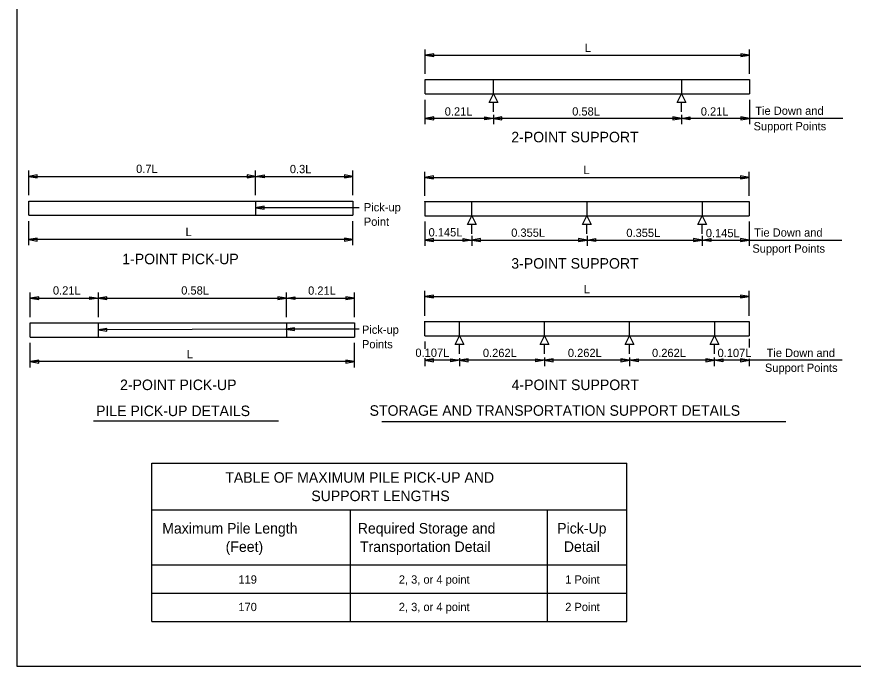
# Model space of a CAD drawing. Extents: x 120517.2 to 120592, y 120519.3 to 120603.1.
# Drawn here: x 120521.21 to 120541.57, y 120571.22 to 120587.02 of the extents above; entities that cross this region are included whole.
import ezdxf

# ---------------------------------------------------------------- set-up
doc = ezdxf.new("R2010")
doc.units = 0
for name, color, linetype in [('ActivePts-ConstElements', 7, 'Continuous'), ('AdhocPoint_dp', 7, 'Continuous'), ('PlotBorder_dp', 7, 'Continuous'), ('TextMisc', 7, 'Continuous')]:
    doc.layers.add(name, color=color, linetype=linetype)

msp = doc.modelspace()

# ---------------------------------------------------------------- linework, layer by layer
at = {"layer": 'ActivePts-ConstElements'}
msp.add_lwpolyline([(120521.209, 120571.217), (120562.259, 120571.217), (120562.259, 120597.163), (120521.209, 120597.163)], close=True, dxfattribs=at)
at = {"layer": 'PlotBorder_dp'}
for p, q in [((120531.151, 120585.633), (120531.151, 120586.226)), ((120539.041, 120585.633), (120539.041, 120586.226)), ((120531.151, 120586.086), (120539.041, 120586.086)), ((120531.151, 120584.408), (120531.151, 120585.004)), ((120539.041, 120585.004), (120539.041, 120584.408)), ((120532.81, 120584.704), (120532.81, 120584.936)), ((120537.386, 120584.704), (120537.386, 120584.936)), ((120532.808, 120584.638), (120532.808, 120584.408)), ((120537.385, 120584.636), (120537.385, 120584.408)), ((120541.313, 120584.548), (120531.151, 120584.548)), ((120521.501, 120582.678), (120521.501, 120583.277)), ((120527.023, 120582.678), (120527.023, 120583.277)), ((120529.39, 120582.678), (120529.39, 120583.277)), ((120531.141, 120582.664), (120531.141, 120583.252)), ((120539.03, 120582.664), (120539.03, 120583.252)), ((120521.501, 120583.137), (120529.39, 120583.137)), ((120531.141, 120583.112), (120539.03, 120583.112)), ((120531.141, 120582.524), (120531.141, 120582.532)), ((120532.283, 120582.524), (120532.283, 120582.527)), ((120535.085, 120582.524), (120535.085, 120582.531)), ((120529.54, 120582.376), (120527.023, 120582.376)), ((120521.501, 120581.46), (120521.501, 120582.048)), ((120529.39, 120581.46), (120529.39, 120582.05)), ((120531.141, 120582.036), (120531.141, 120581.447)), ((120532.286, 120581.736), (120532.286, 120581.967)), ((120535.086, 120581.736), (120535.086, 120581.967)), ((120537.888, 120581.736), (120537.888, 120581.967)), ((120539.03, 120582.036), (120539.03, 120581.447)), ((120529.39, 120581.6), (120521.501, 120581.6)), ((120531.141, 120581.587), (120541.285, 120581.587)), ((120532.285, 120581.691), (120532.285, 120581.447)), ((120535.088, 120581.691), (120535.088, 120581.447)), ((120537.89, 120581.691), (120537.89, 120581.447)), ((120521.538, 120579.713), (120521.538, 120580.313)), ((120523.195, 120579.713), (120523.195, 120580.313)), ((120527.771, 120579.713), (120527.771, 120580.313)), ((120529.428, 120579.713), (120529.428, 120580.313)), ((120531.141, 120579.747), (120531.141, 120580.354)), ((120539.03, 120579.747), (120539.03, 120580.354)), ((120521.538, 120580.173), (120529.428, 120580.173)), ((120531.141, 120580.214), (120539.03, 120580.214)), ((120531.141, 120579.607), (120531.141, 120579.615)), ((120532.283, 120579.607), (120532.283, 120579.61)), ((120535.085, 120579.607), (120535.085, 120579.613)), ((120527.761, 120579.42), (120523.195, 120579.403)), ((120529.546, 120579.42), (120527.761, 120579.42)), ((120521.538, 120578.489), (120521.538, 120579.085)), ((120529.428, 120578.489), (120529.428, 120579.085)), ((120531.141, 120579.118), (120531.141, 120578.938)), ((120539.03, 120579.181), (120539.03, 120578.971)), ((120531.986, 120578.818), (120531.986, 120579.05)), ((120534.053, 120578.818), (120534.053, 120579.05)), ((120536.12, 120578.818), (120536.12, 120579.05)), ((120538.188, 120578.818), (120538.188, 120579.05)), ((120531.141, 120578.714), (120531.141, 120578.522)), ((120541.298, 120578.662), (120531.141, 120578.662)), ((120531.985, 120578.717), (120531.985, 120578.522)), ((120534.051, 120578.73), (120534.051, 120578.522)), ((120536.118, 120578.73), (120536.118, 120578.522)), ((120538.185, 120578.728), (120538.185, 120578.522)), ((120539.03, 120578.7), (120539.03, 120578.522)), ((120529.428, 120578.629), (120521.538, 120578.629)), ((120531.985, 120578.587), (120531.985, 120578.522)), ((120536.121, 120578.522), (120536.121, 120578.522)), ((120527.583, 120577.177), (120523.078, 120577.177)), ((120530.09, 120577.17), (120539.927, 120577.17)), ((120524.495, 120576.156), (120536.056, 120576.156)), ((120524.495, 120572.305), (120524.495, 120576.156)), ((120536.056, 120572.305), (120536.056, 120576.156)), ((120524.495, 120575.02), (120536.056, 120575.02)), ((120529.328, 120572.305), (120529.328, 120575.02)), ((120534.123, 120572.305), (120534.123, 120575.02)), ((120524.495, 120573.684), (120536.056, 120573.684)), ((120524.495, 120572.995), (120536.056, 120572.995)), ((120524.495, 120572.305), (120536.056, 120572.305))]:
    msp.add_line(p, q, dxfattribs=at)
for points in [[(120531.151, 120586.086), (120531.36, 120586.051), (120531.36, 120586.122)], [(120539.041, 120586.086), (120538.833, 120586.122), (120538.833, 120586.051)], [(120532.808, 120585.144), (120532.913, 120584.936), (120532.703, 120584.936)], [(120537.385, 120585.144), (120537.49, 120584.936), (120537.28, 120584.936)], [(120531.151, 120584.548), (120531.36, 120584.513), (120531.36, 120584.584)], [(120532.808, 120584.548), (120532.6, 120584.513), (120532.6, 120584.584)], [(120532.808, 120584.548), (120533.016, 120584.513), (120533.016, 120584.584)], [(120537.385, 120584.548), (120537.176, 120584.584), (120537.176, 120584.513)], [(120537.385, 120584.548), (120537.593, 120584.584), (120537.593, 120584.513)], [(120539.041, 120584.548), (120538.833, 120584.584), (120538.833, 120584.513)], [(120521.501, 120583.137), (120521.71, 120583.102), (120521.71, 120583.173)], [(120527.023, 120583.137), (120526.815, 120583.173), (120526.815, 120583.102)], [(120527.023, 120583.137), (120527.231, 120583.173), (120527.231, 120583.102)], [(120529.39, 120583.137), (120529.182, 120583.173), (120529.182, 120583.102)], [(120531.141, 120583.112), (120531.35, 120583.077), (120531.35, 120583.148)], [(120539.03, 120583.112), (120538.821, 120583.148), (120538.821, 120583.077)], [(120527.023, 120582.376), (120527.231, 120582.341), (120527.231, 120582.411)], [(120532.285, 120582.176), (120532.39, 120581.967), (120532.18, 120581.967)], [(120535.085, 120582.176), (120535.19, 120581.967), (120534.98, 120581.967)], [(120537.886, 120582.176), (120537.991, 120581.967), (120537.781, 120581.967)], [(120521.501, 120581.6), (120521.71, 120581.564), (120521.71, 120581.635)], [(120529.39, 120581.6), (120529.182, 120581.635), (120529.182, 120581.564)], [(120531.141, 120581.587), (120531.35, 120581.552), (120531.35, 120581.623)], [(120532.285, 120581.587), (120532.076, 120581.552), (120532.076, 120581.623)], [(120532.285, 120581.587), (120532.493, 120581.552), (120532.493, 120581.623)], [(120535.088, 120581.587), (120534.88, 120581.623), (120534.88, 120581.552)], [(120535.088, 120581.587), (120535.296, 120581.623), (120535.296, 120581.552)], [(120537.89, 120581.587), (120537.681, 120581.623), (120537.681, 120581.552)], [(120537.89, 120581.587), (120538.098, 120581.623), (120538.098, 120581.552)], [(120539.03, 120581.587), (120538.821, 120581.623), (120538.821, 120581.552)], [(120521.538, 120580.173), (120521.746, 120580.138), (120521.746, 120580.208)], [(120523.195, 120580.173), (120522.987, 120580.138), (120522.987, 120580.208)], [(120523.195, 120580.173), (120523.403, 120580.138), (120523.403, 120580.208)], [(120527.771, 120580.173), (120527.563, 120580.208), (120527.563, 120580.138)], [(120527.771, 120580.173), (120527.98, 120580.208), (120527.98, 120580.138)], [(120529.428, 120580.173), (120529.22, 120580.208), (120529.22, 120580.138)], [(120531.141, 120580.214), (120531.35, 120580.178), (120531.35, 120580.249)], [(120539.03, 120580.214), (120538.821, 120580.249), (120538.821, 120580.178)], [(120523.195, 120579.403), (120523.403, 120579.369), (120523.403, 120579.439)], [(120527.761, 120579.42), (120527.97, 120579.385), (120527.97, 120579.455)], [(120531.985, 120579.258), (120532.09, 120579.05), (120531.88, 120579.05)], [(120534.051, 120579.258), (120534.156, 120579.05), (120533.946, 120579.05)], [(120536.118, 120579.258), (120536.223, 120579.05), (120536.013, 120579.05)], [(120538.186, 120579.258), (120538.291, 120579.05), (120538.081, 120579.05)], [(120521.538, 120578.629), (120521.746, 120578.594), (120521.746, 120578.665)], [(120529.428, 120578.629), (120529.22, 120578.665), (120529.22, 120578.594)], [(120531.141, 120578.662), (120531.35, 120578.626), (120531.35, 120578.697)], [(120531.985, 120578.662), (120531.776, 120578.626), (120531.776, 120578.697)], [(120531.985, 120578.662), (120532.193, 120578.626), (120532.193, 120578.697)], [(120534.051, 120578.662), (120533.843, 120578.626), (120533.843, 120578.697)], [(120534.051, 120578.662), (120534.26, 120578.626), (120534.26, 120578.697)], [(120536.118, 120578.662), (120535.91, 120578.697), (120535.91, 120578.626)], [(120536.125, 120578.662), (120536.333, 120578.697), (120536.333, 120578.626)], [(120538.185, 120578.662), (120537.976, 120578.697), (120537.976, 120578.626)], [(120538.185, 120578.662), (120538.393, 120578.697), (120538.393, 120578.626)], [(120539.03, 120578.662), (120538.821, 120578.697), (120538.821, 120578.626)]]:
    msp.add_lwpolyline(points, close=True, dxfattribs=at)
at = {"layer": 'TextMisc'}
for p, q in [((120531.151, 120585.493), (120539.041, 120585.493)), ((120531.151, 120585.144), (120531.151, 120585.493)), ((120532.808, 120585.144), (120532.808, 120585.493)), ((120537.385, 120585.493), (120537.385, 120585.144)), ((120539.041, 120585.493), (120539.041, 120585.144)), ((120531.151, 120585.144), (120539.041, 120585.144)), ((120521.501, 120582.538), (120529.39, 120582.538)), ((120521.501, 120582.19), (120521.501, 120582.538)), ((120527.023, 120582.538), (120527.023, 120582.19)), ((120529.39, 120582.538), (120529.39, 120582.19)), ((120531.141, 120582.524), (120539.03, 120582.524)), ((120531.141, 120582.524), (120531.141, 120582.176)), ((120532.283, 120582.176), (120532.283, 120582.524)), ((120532.285, 120582.176), (120532.285, 120582.524)), ((120535.085, 120582.524), (120535.085, 120582.176)), ((120535.233, 120582.524), (120539.03, 120582.524)), ((120537.886, 120582.524), (120537.886, 120582.176)), ((120539.03, 120582.524), (120539.03, 120582.176)), ((120521.501, 120582.19), (120529.39, 120582.19)), ((120531.141, 120582.176), (120539.03, 120582.176)), ((120521.538, 120579.573), (120529.428, 120579.573)), ((120521.538, 120579.225), (120521.538, 120579.573)), ((120523.195, 120579.225), (120523.195, 120579.573)), ((120527.771, 120579.573), (120527.771, 120579.225)), ((120529.428, 120579.573), (120529.428, 120579.225)), ((120531.141, 120579.607), (120539.03, 120579.607)), ((120531.141, 120579.258), (120531.141, 120579.607)), ((120531.985, 120579.258), (120531.985, 120579.607)), ((120534.051, 120579.258), (120534.051, 120579.607)), ((120535.233, 120579.607), (120539.03, 120579.607)), ((120536.118, 120579.258), (120536.118, 120579.607)), ((120538.186, 120579.607), (120538.186, 120579.258)), ((120539.03, 120579.607), (120539.03, 120579.258)), ((120521.538, 120579.225), (120529.428, 120579.225)), ((120531.141, 120579.258), (120539.03, 120579.258))]:
    msp.add_line(p, q, dxfattribs=at)

# ---------------------------------------------------------------- texts
at = {"layer": 'AdhocPoint_dp'}
for s, height, p in [('L', 0.202, (120535.031, 120586.163)), ('0.21L', 0.2016, (120531.624, 120584.616)), ('0.58L', 0.2016, (120534.726, 120584.617)), ('0.21L', 0.2016, (120537.856, 120584.617)), ('Tie Down and', 0.2016, (120539.182, 120584.634)), ('Support Points', 0.2016, (120539.14, 120584.258)), ('2-POINT SUPPORT', 0.256, (120533.244, 120583.966)), ('0.7L', 0.2016, (120524.114, 120583.221)), ('0.3L', 0.2016, (120527.855, 120583.215)), ('L', 0.202, (120535.001, 120583.192)), ('L', 0.202, (120525.318, 120581.684)), ('0.145L', 0.2016, (120531.231, 120581.676)), ('0.355L', 0.2016, (120533.242, 120581.667)), ('0.355L', 0.2016, (120536.044, 120581.662)), ('0.145L', 0.2016, (120537.978, 120581.658)), ('Tie Down and', 0.2016, (120539.156, 120581.67)), ('Support Points', 0.2016, (120539.111, 120581.28)), ('1-POINT PICK-UP', 0.256, (120523.777, 120581)), ('3-POINT SUPPORT', 0.256, (120533.244, 120580.892)), ('L', 0.202, (120535.01, 120580.293)), ('0.21L', 0.2016, (120522.09, 120580.261)), ('0.58L', 0.2016, (120525.212, 120580.261)), ('0.21L', 0.2016, (120528.3, 120580.257)), ('L', 0.202, (120525.349, 120578.713)), ('0.107L', 0.2016, (120530.911, 120578.746)), ('0.262L', 0.2016, (120532.553, 120578.741)), ('0.262L', 0.2016, (120534.621, 120578.741)), ('0.262L', 0.2016, (120536.669, 120578.741)), ('0.107L', 0.2016, (120538.264, 120578.741)), ('Tie Down and', 0.2016, (120539.458, 120578.742)), ('Support Points', 0.2016, (120539.417, 120578.38)), ('2-POINT PICK-UP', 0.256, (120523.724, 120577.937)), ('4-POINT SUPPORT', 0.256, (120533.252, 120577.937)), ('PILE PICK-UP DETAILS', 0.256, (120523.139, 120577.304)), ('STORAGE AND TRANSPORTATION SUPPORT DETAILS', 0.256, (120529.796, 120577.312)), ('119', 0.2016, (120526.604, 120573.227)), ('2, 3, or 4 point', 0.2016, (120530.507, 120573.227)), ('1 Point', 0.2016, (120534.557, 120573.227)), ('170', 0.2016, (120526.603, 120572.559)), ('2, 3, or 4 point', 0.2016, (120530.507, 120572.559)), ('2 Point', 0.2016, (120534.557, 120572.559))]:
    msp.add_text(s, height=height, dxfattribs=at).set_placement(p)
at = {"layer": 'PlotBorder_dp'}
for s, height, p in [('Pick-up ', 0.2016, (120529.656, 120582.286)), ('Point', 0.2016, (120529.656, 120581.934)), ('Pick-up ', 0.2016, (120529.61, 120579.306)), ('Points', 0.2016, (120529.61, 120578.954)), ('TABLE OF MAXIMUM PILE PICK-UP AND', 0.256, (120526.283, 120575.683)), ('SUPPORT LENGTHS', 0.256, (120528.378, 120575.235)), ('Maximum Pile Length', 0.256, (120524.749, 120574.447)), ('Required Storage and', 0.256, (120529.508, 120574.447)), ('Pick-Up', 0.256, (120534.362, 120574.447)), ('(Feet)', 0.256, (120526.293, 120573.999)), ('Transportation Detail  ', 0.256, (120529.561, 120573.999)), ('Detail', 0.256, (120534.523, 120573.999))]:
    msp.add_text(s, height=height, dxfattribs=at).set_placement(p)

doc.saveas('drawing.dxf')
